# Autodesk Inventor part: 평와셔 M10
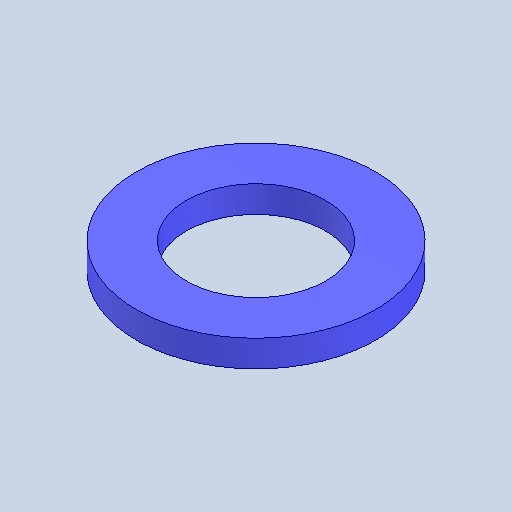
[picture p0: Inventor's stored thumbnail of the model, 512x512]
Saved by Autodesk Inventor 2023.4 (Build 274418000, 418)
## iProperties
Created: 2024-04
Part Number: 평와셔 M10
Material: 강철, 연강
Document SubType Name: Modeling
Designer: EDU
Density: 7.86 g/cm^3
Appearance: 기본값
Author: jhkim
Sending System: Autodesk Inventor 2025
Preprocessor: ST-DEVELOPER v20
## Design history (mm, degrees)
node "평와셔 M101"
node "솔리드2"
node "솔리드1"
